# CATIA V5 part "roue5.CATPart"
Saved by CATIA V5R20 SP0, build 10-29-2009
Part number: roue5
Bounding box of the stored display mesh (mm): x -325 to -290, y -1051 to -1019, z 0.01 to 31.99
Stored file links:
  D:\Dropbox\Pack 1 sylvain\mmoreau\mmoreau\mmoreau\fin\roue5.CATPart
  U:\think motion\fin\think motion2.CATProduct
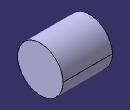
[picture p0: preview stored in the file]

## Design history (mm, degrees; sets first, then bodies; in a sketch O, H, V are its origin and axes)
Set1
  Plane1: linked copy from another document
  Point1: linked copy from another document
Body1 (main body)
  Sketch1 on Plane1, origin (-325, 0, 0), H (0, 1, 0), V (0, 0, 1)
    circle A1 centre (-1035, 16) radius 16
    point P1 (-1035, 16)
    reference projected point E1 (-1035, 16) from Point1
    coincidence: E1 P1
    tangency: A1 H
  Pad1: profile Sketch1, direction (1, 0, 0), length 35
